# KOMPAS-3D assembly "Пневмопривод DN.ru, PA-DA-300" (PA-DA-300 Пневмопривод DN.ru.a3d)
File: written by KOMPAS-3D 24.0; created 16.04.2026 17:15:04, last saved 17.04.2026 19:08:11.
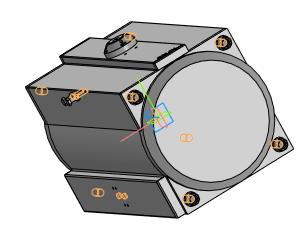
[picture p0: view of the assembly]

Document properties: Автор: DN.ru; Полное имя файла: C:\Работа\PA-DA-х Пневмопривод DN.ru\300\исходные материалы\PA-DA-300 Пневмопривод DN.ru.a3d

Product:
- Component [detail]: Пневмопривод DN.ru  | designation PA-DA-300  | qty 1  | pos. 1  | Масса: 110; Раздел спецификации: Прочие изделия; Примечание: D290-00302; Автор: DN.ru; source file: PA-DA-300 Пневмопривод DN.ru.m3d
- Component [standard]: Болт М10-6gx50 ГОСТ 7805-70  | qty 1  | pos. 2  | Масса: 0.04195; Раздел спецификации: Стандартные изделия; Рассекать на разрезах: no
- Component [standard]: Болт М10-6gx50 ГОСТ 7805-70  | qty 1  | Масса: 0.04195; Раздел спецификации: Стандартные изделия; Рассекать на разрезах: no
- Component [standard]: Гайка М10-6H ГОСТ 5915-70  | qty 1  | pos. 3  | Масса: 0.01206; Раздел спецификации: Стандартные изделия; Рассекать на разрезах: no
- Component [standard]: Гайка М10-6H ГОСТ 5915-70  | qty 1  | Масса: 0.01206; Раздел спецификации: Стандартные изделия; Рассекать на разрезах: no
- Component [standard]: Винт М20-6gx40 ГОСТ 11738-84  | qty 8  | Масса: 0.17343; Раздел спецификации: Стандартные изделия; Рассекать на разрезах: no
- Part/product: Пневмопривод DN.ru  | designation PA-DA-300
    Масса: 110
    Раздел спецификации: Прочие изделия
    Примечание: D290-00302

Expressions: D290-00302
Referenced files in C:\Работа\PA-DA-х Пневмопривод DN.ru\300\исходные материалы\: PA-DA-300 Пневмопривод DN.ru.m3d
Referenced files in C:\Program Files\ASCON\KOMPAS-3D v24\Libs\PolynomLib\DATA\vault\Methods\Kompas\3D\: PLib_Bolt_1_900.m3d, PLib_Nut_OST92_900.m3d, PLib_Screw_GOST_11738_1500.m3d
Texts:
  PA-DA-300
  Крепежное изделие ГОСТ
  BOSimple***PART:f6352c65-8636-7196-6402-d592979e6031***SHORTLOC:Root±30±20±10±80±10±©{}30±©{BASE}130±30[Нет;Без покрытия;Без указания материала;50;10;17;1,5;-]
  BOSimple***PART:2c395b93-8c4a-cf39-bcf6-f45056cee6ca***SHORTLOC:Root±30±10±20±©{}110±10±50±60[Нет;Без покрытия;Без указания материала;-;10;1,5;17]
  BOSimple***PART:939ec6a4-9eca-958d-2272-ec7bb45f395d***SHORTLOC:Root±30±20±10±80±10±GMC90[Нет;Без покрытия;Без указания материала;2,5;-;40;20]
  Программные изделия  и базы данных
  PA-DA-300 Пневмопривод DN.ru
  Болт М10-6gx50 ГОСТ 7805-70 (1)
  hole1
  hole2
  Болт М10-6gx50 ГОСТ 7805-70 (2)
  Гайка М10-6H ГОСТ 5915-70 (1)
  bcut1
  hcut1
  cut1
  Гайка М10-6H ГОСТ 5915-70 (2)
  Винт М20-6gx40 ГОСТ 11738-84 (1)
  Винт М20-6gx40 ГОСТ 11738-84 (2)
  Винт М20-6gx40 ГОСТ 11738-84 (3)
  Винт М20-6gx40 ГОСТ 11738-84 (4)
  Винт М20-6gx40 ГОСТ 11738-84 (5)
  Винт М20-6gx40 ГОСТ 11738-84 (6)
  Винт М20-6gx40 ГОСТ 11738-84 (7)
  Винт М20-6gx40 ГОСТ 11738-84 (8)
  Plane. Начало координат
